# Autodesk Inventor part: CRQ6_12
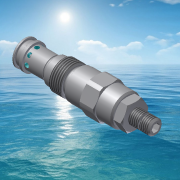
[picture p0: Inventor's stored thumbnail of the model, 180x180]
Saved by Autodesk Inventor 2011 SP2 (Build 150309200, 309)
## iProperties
Created: 2014-06
Part Number: CRQ6_12
Document SubType Name: Modeling
Designer: dorohin
Density: 1 g/cm^3
Author: dorohin
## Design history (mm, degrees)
node "Твердое тело1"
derived "CRQ6_12.iam"
node "0112702.ipt:1"
node "0122447-01(PT).ipt:1"
node "0112816.ipt:1"
node "0112703.ipt:1"
node "0112704.ipt:1"
node "0532040.ipt:1"
node "0112827.ipt:1"
